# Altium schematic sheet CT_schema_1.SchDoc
size 522 x 479 mm
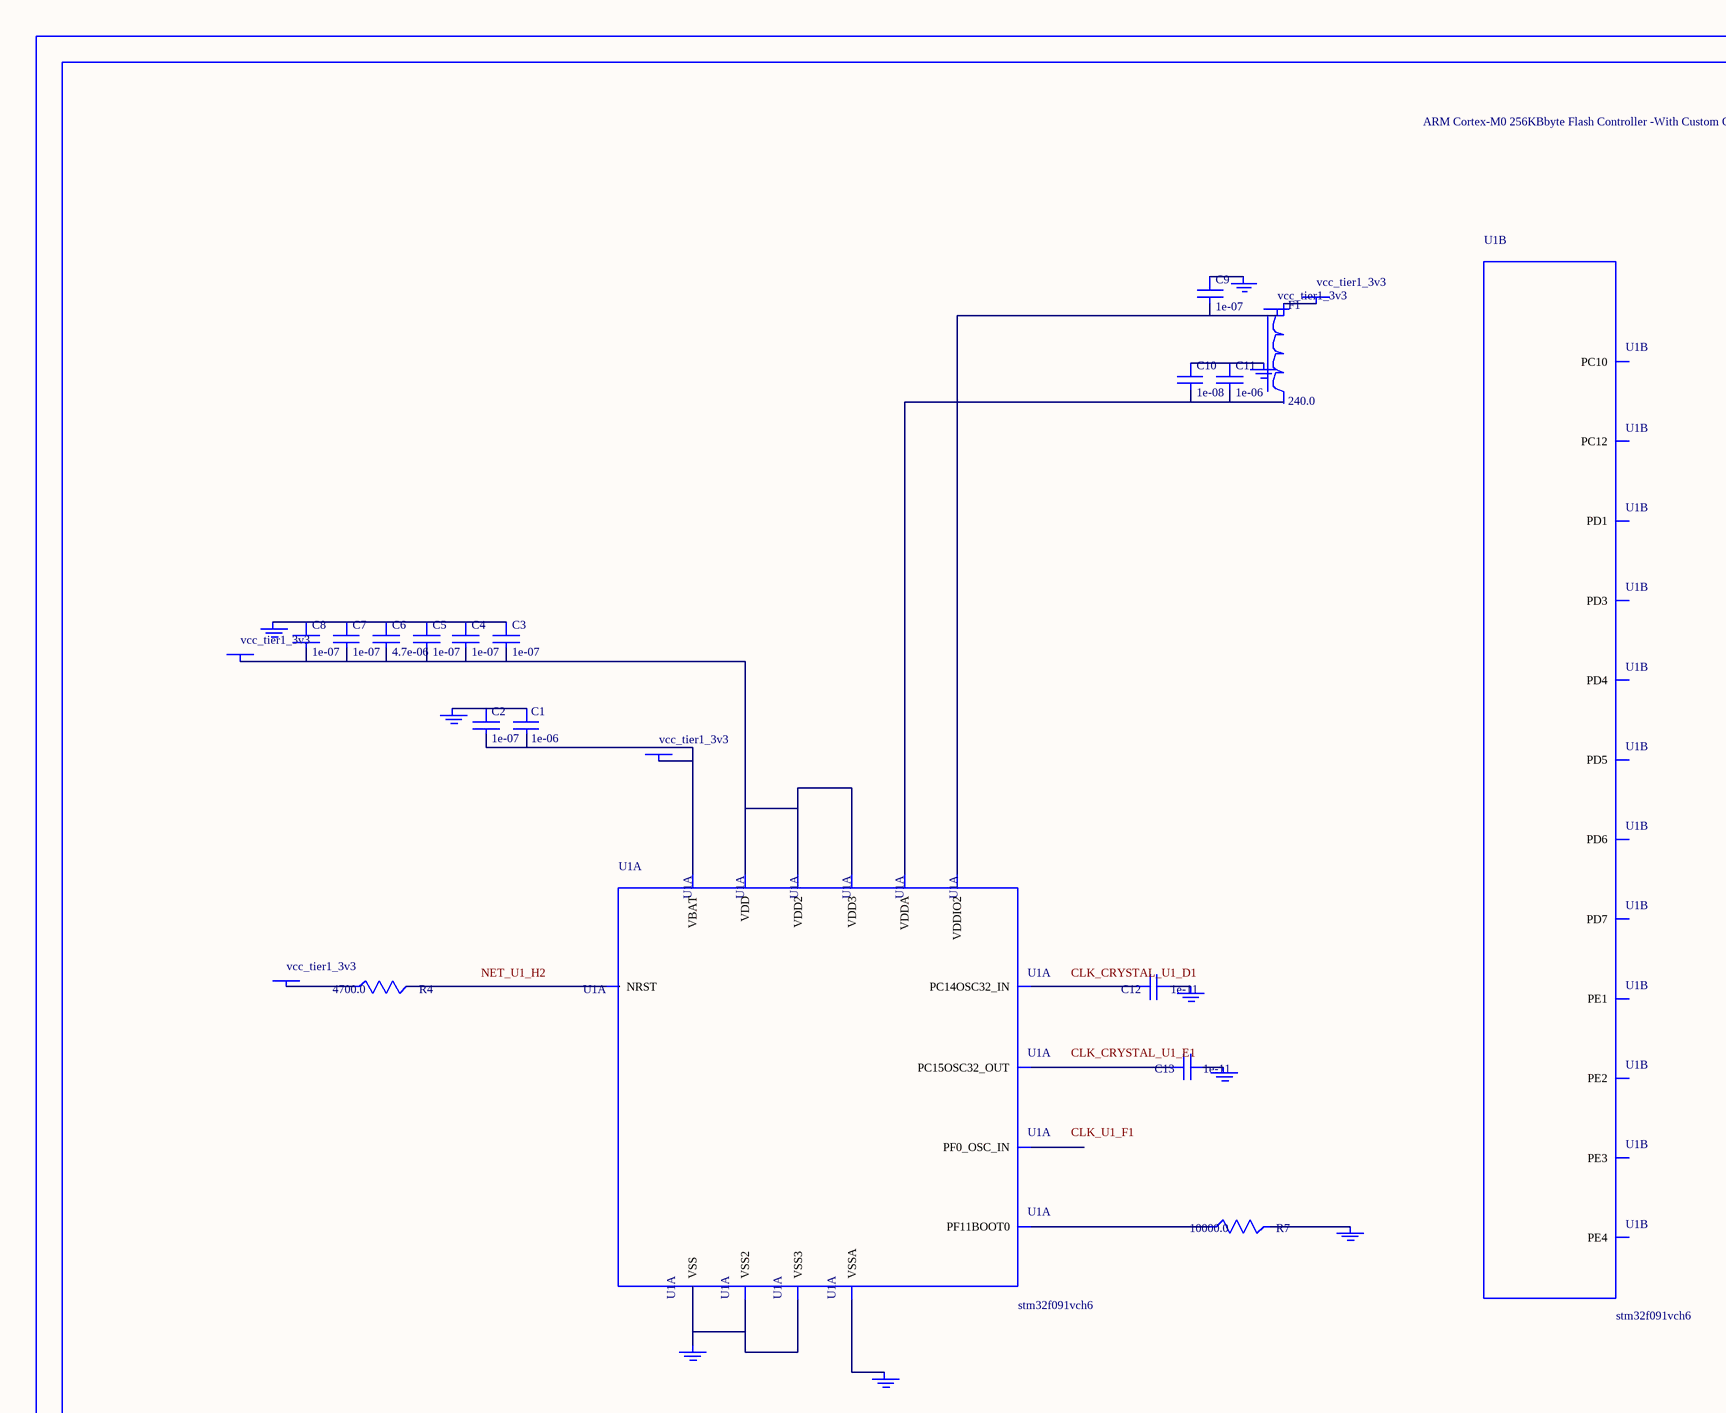
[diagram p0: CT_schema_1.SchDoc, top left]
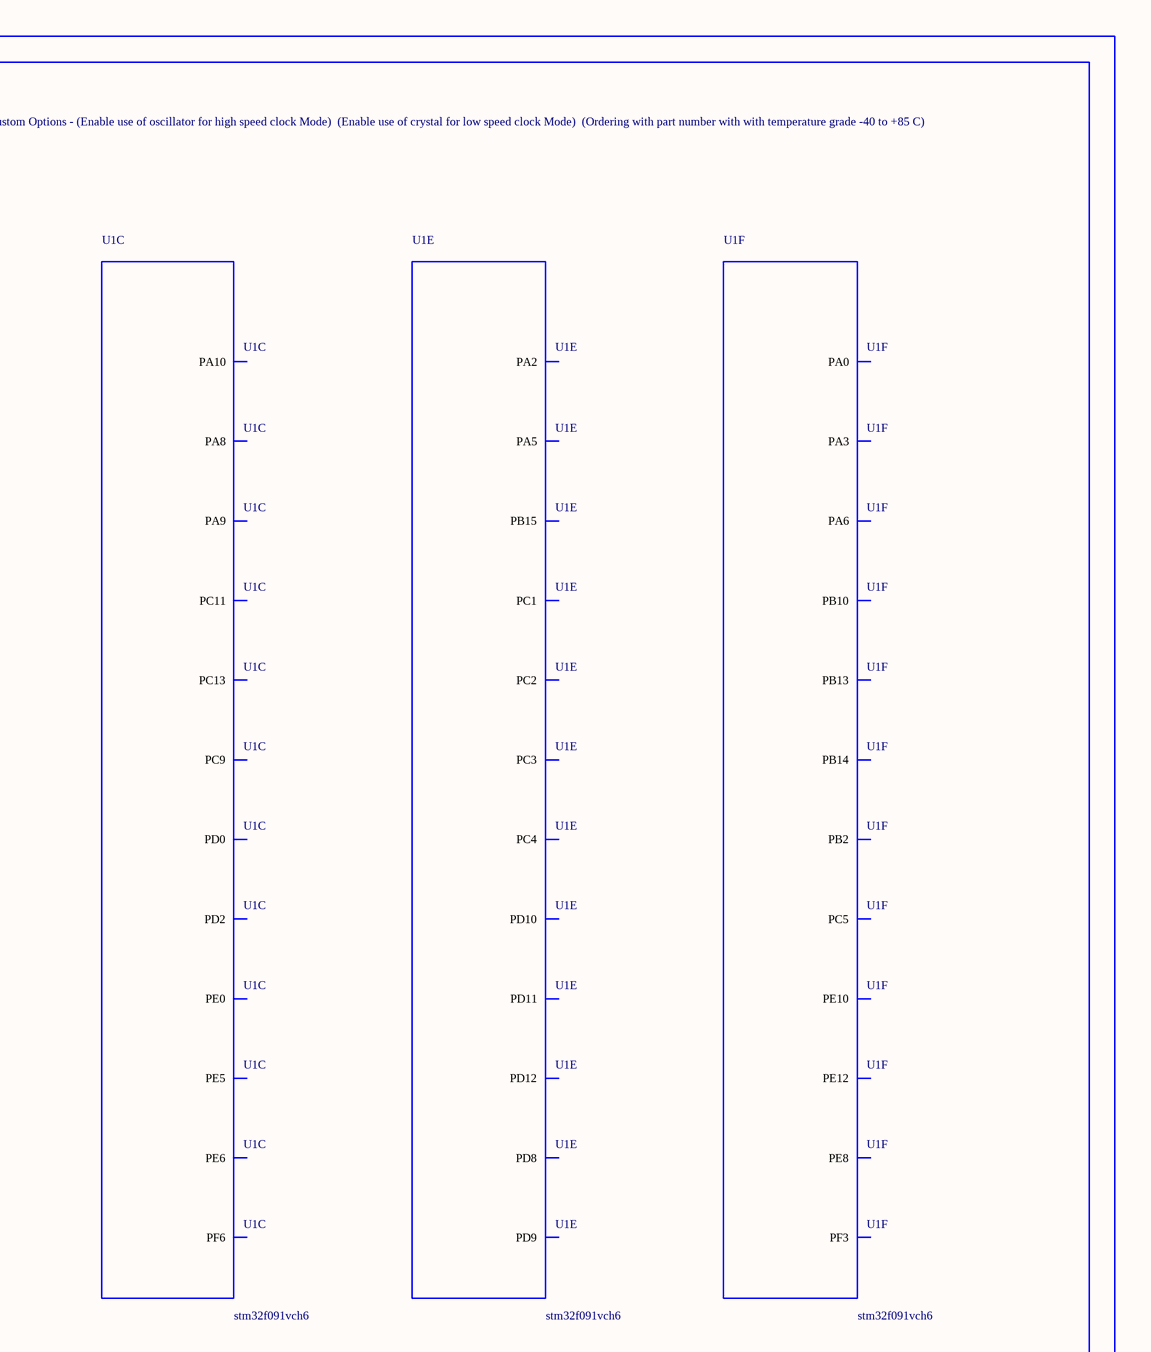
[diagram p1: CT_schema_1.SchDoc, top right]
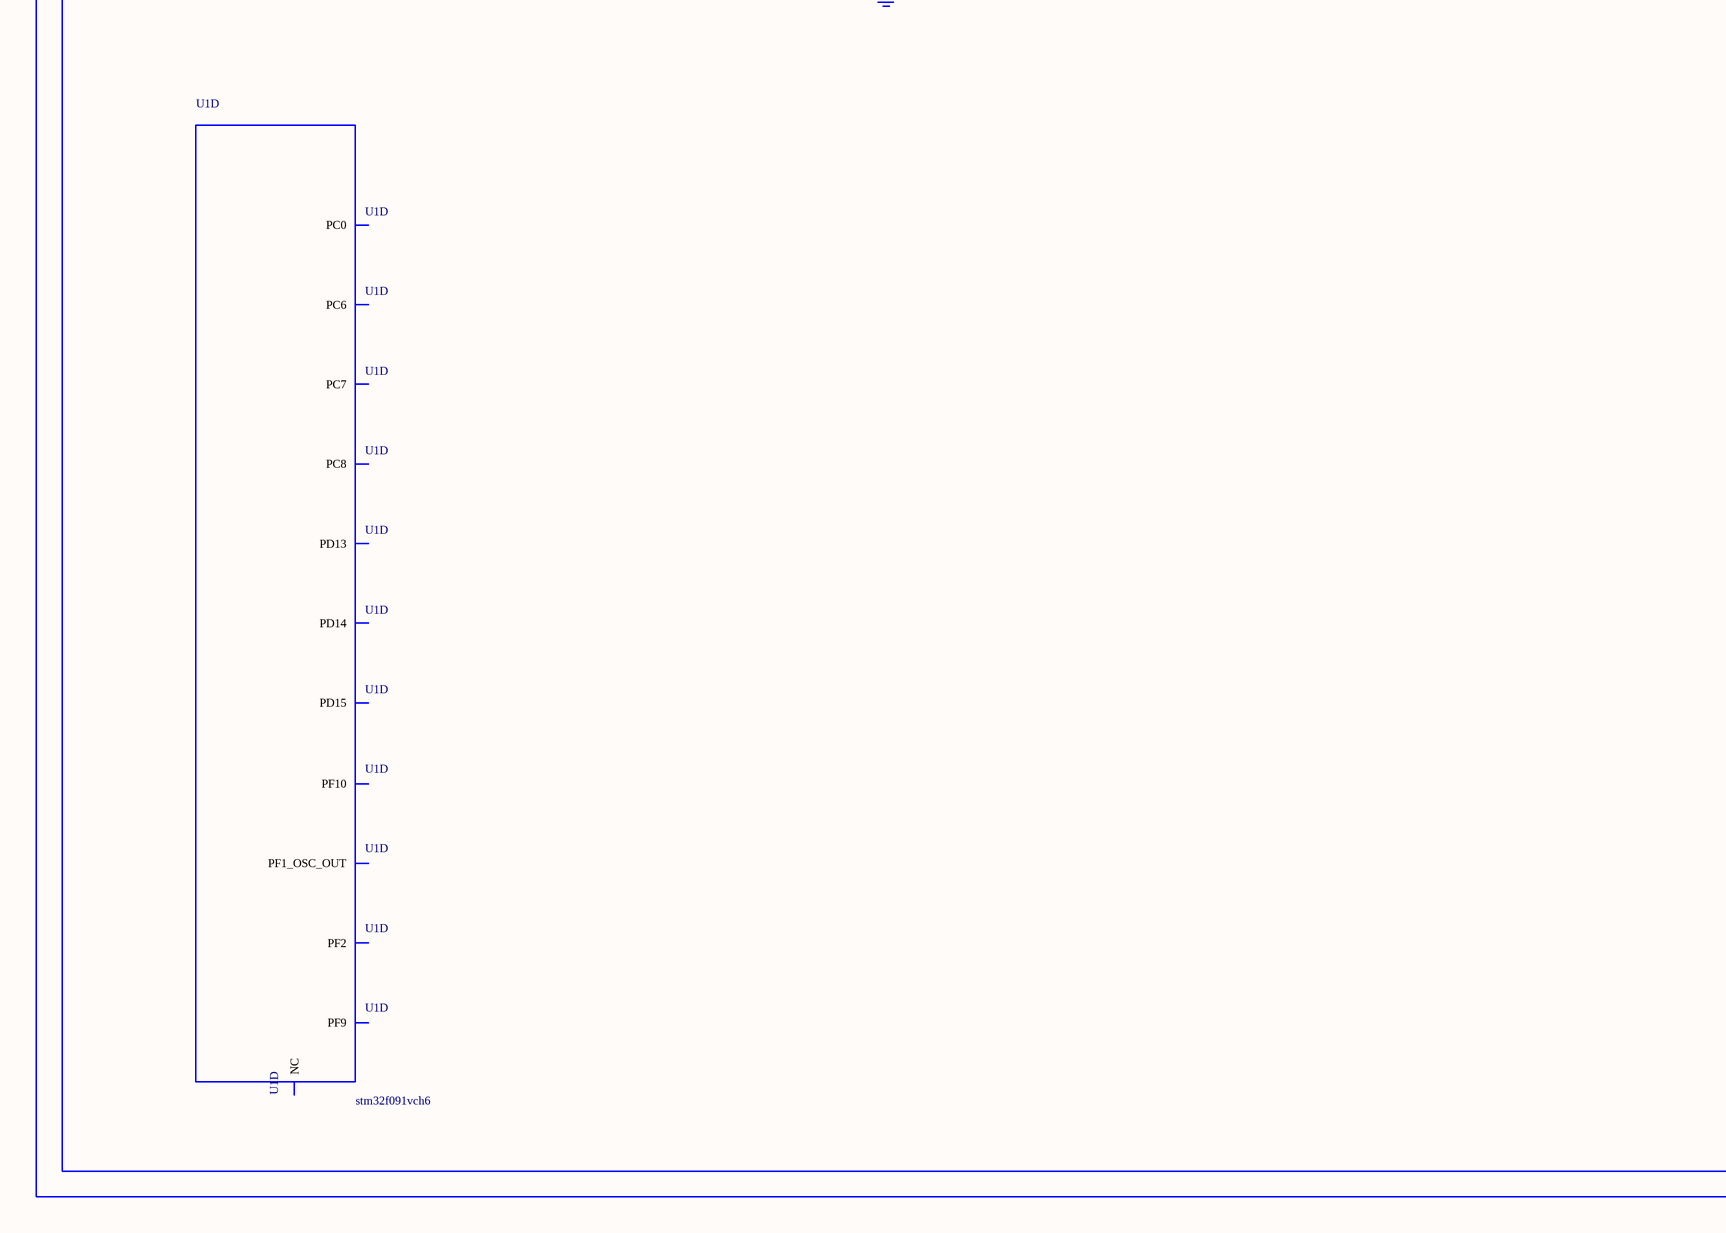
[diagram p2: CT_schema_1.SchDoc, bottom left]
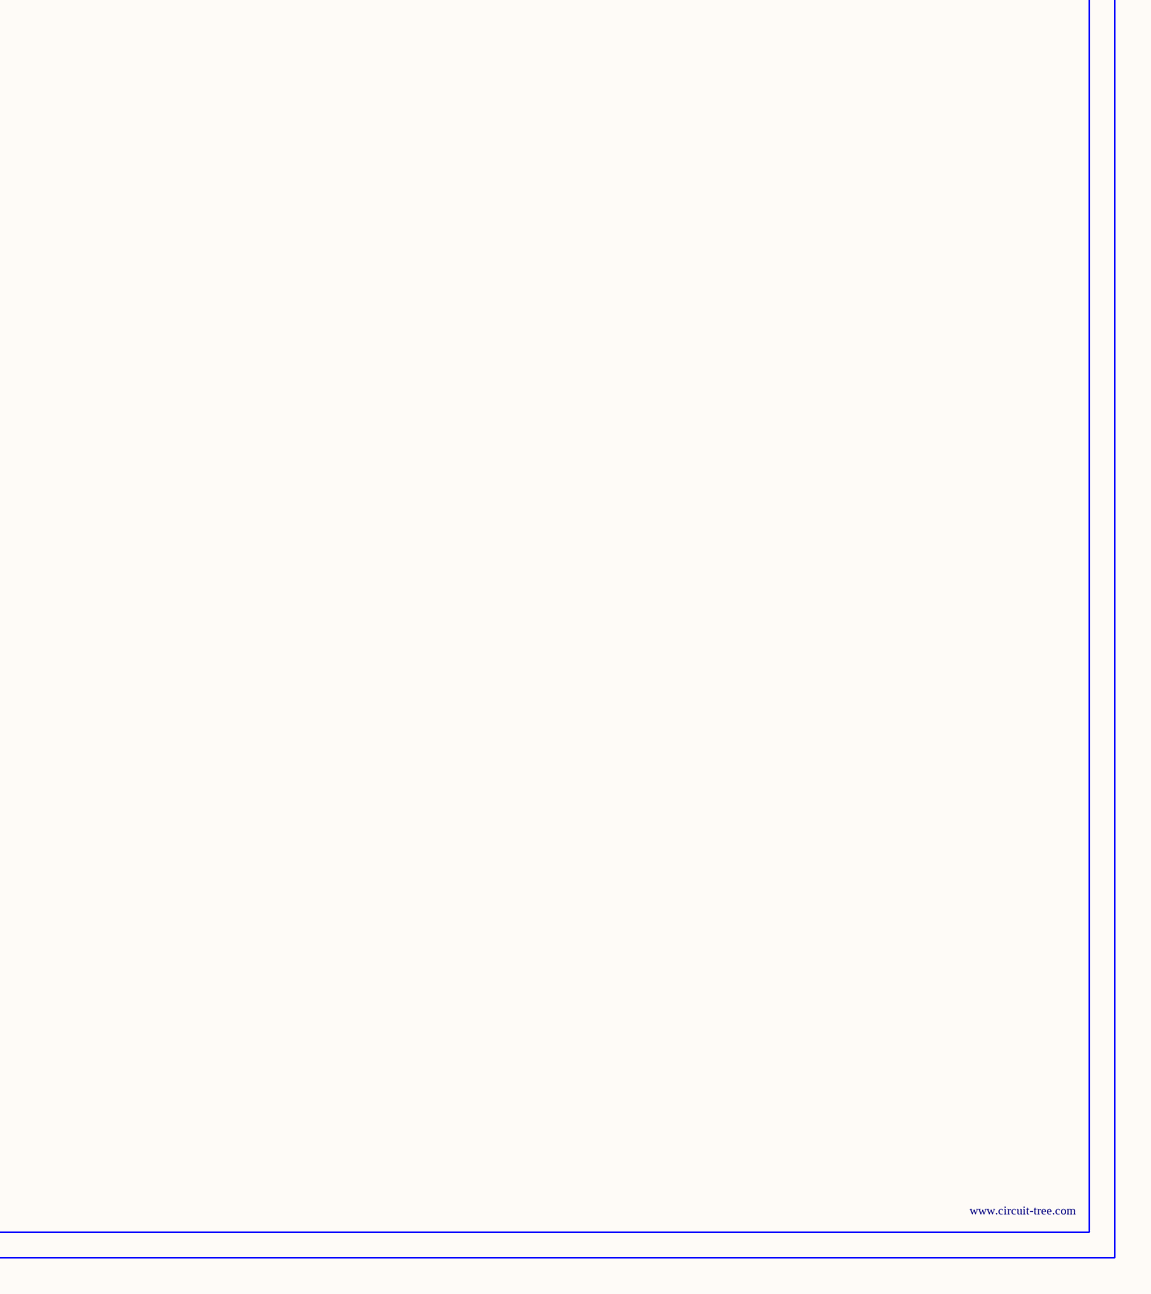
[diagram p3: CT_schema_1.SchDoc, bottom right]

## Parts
BORDER0  (no value)
C1  1e-06  [C0603]
C2  1e-07  [C0603]
C3  1e-07  [C0603]
C4  1e-07  [C0603]
C5  1e-07  [C0603]
C6  4.7e-06  [C0603]
C7  1e-07  [C0603]
C8  1e-07  [C0603]
C9  1e-07  [C0603]
C10  1e-08  [C0603]
C11  1e-06  [C0603]
C12  1e-11  [C0402]
C13  1e-11  [C0402]
F1  240.0  [L0603]
GND_INSTANCE_0_0  (no value)
GND_INSTANCE_0_1  (no value)
GND_INSTANCE_0_2  (no value)
GND_INSTANCE_0_3  (no value)
GND_INSTANCE_0_4  (no value)
GND_INSTANCE_0_5  (no value)
GND_INSTANCE_0_6  (no value)
GND_INSTANCE_0_7  (no value)
GND_INSTANCE_0_8  (no value)
POWER_INSTANCE_0_0  vcc_tier1_3v3
POWER_INSTANCE_0_1  vcc_tier1_3v3
POWER_INSTANCE_0_2  vcc_tier1_3v3
POWER_INSTANCE_0_3  vcc_tier1_3v3
POWER_INSTANCE_0_4  vcc_tier1_3v3
R4  4700.0  [R0603]
R7  10000.0  [R0603]
U1  stm32f091vch6  [UFBGA100]  (parts A,B,C,D,E,F of 9)

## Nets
NetC1_1: C1.1 C2.1 GND_INSTANCE_0_0.0(GND)
NetC1_2: C1.2 C2.2 POWER_INSTANCE_0_0.0(PWR) U1.E2(VBAT)
NetC3_1: C3.1 C4.1 C5.1 C6.1 C7.1 C8.1 GND_INSTANCE_0_2.0(GND)
NetC3_2: C3.2 C4.2 C5.2 C6.2 C7.2 C8.2 POWER_INSTANCE_0_2.0(PWR) U1.C4(VDD) U1.G12(VDD2) U1.H3(VDD3)
NetC9_1: C9.1 GND_INSTANCE_0_3.0(GND)
NetC9_2: C9.2 POWER_INSTANCE_0_3.0(PWR) U1.G11(VDDIO2)
NetC10_1: C10.1 C11.1 GND_INSTANCE_0_1.0(GND)
NetC10_2: C10.2 C11.2 U1.M1(VDDA)
NetC12_1: C12.1 GND_INSTANCE_0_5.0(GND)
NetC12_2: C12.2 U1.D1(PC14OSC32_IN)
NetC13_1: C13.1 GND_INSTANCE_0_6.0(GND)
NetC13_2: C13.2 U1.E1(PC15OSC32_OUT)
NetF1_1: F1.1 POWER_INSTANCE_0_1.0(PWR)
NetGND_INSTANCE_0_4_0: GND_INSTANCE_0_4.0(GND) R7.2
NetGND_INSTANCE_0_7_0: GND_INSTANCE_0_7.0(GND) U1.K1(VSSA)
NetGND_INSTANCE_0_8_0: GND_INSTANCE_0_8.0(GND) U1.D3(VSS) U1.F11(VSS2) U1.F12(VSS3)
NetPOWER_INSTANCE_0_4_0: POWER_INSTANCE_0_4.0(PWR) R4.1
NetR4_2: R4.2 U1.H2(NRST)
NetR7_1: R7.1 U1.A4(PF11BOOT0)

Not connected (* = marked no-connect by the designer): F1 2; U1 A1(PE3) A2(PE1) A5(PD7) A6(PD5) B1(PE4) B2(PE2) B6(PD6) B7(PD4) B8(PD3) B9(PD1) B10(PC12) B11(PC10) C1(PC13) C2(PE5) C3(PE0) C8(PD2) C9(PD0) C10(PC11) C11(PF6) C12(PA10) D2(PE6) D10(PA9) D11(PA8) D12(PC9) E3(NC) E10(PC8) E11(PC7) E12(PC6) F1(PF0_OSC_IN) F2(PF9) G1(PF1_OSC_OUT) G2(PF10) H1(PC0) H10(PD15) H11(PD14) H12(PD13) J1(PF2) J2(PC1) J3(PC2) J10(PD12) J11(PD11) J12(PD10) K2(PC3) K3(PA2) K4(PA5) K5(PC4) K8(PD9) K9(PD8) K10(PB15) K11(PB14) K12(PB13) L1(PF3) L2(PA0) L3(PA3) L4(PA6) L5(PC5) L6(PB2) L7(PE8) L8(PE10) L9(PE12) L10(PB10)

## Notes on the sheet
- Labels drawn without touching a wire or pin: CLK_CRYSTAL_U1_D1, CLK_CRYSTAL_U1_E1, CLK_U1_F1, NET_U1_H2

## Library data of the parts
BORDER0 = BORDER_PAGE0
C1 C11 = C0603C105K3RACTU
C2-C5 C7-C9 = 06035C104K4Z2A
C6 = GRM188R6YA475KE15D
C10 = 06035C103K4Z2A
C12 C13 = C0402C100K3GACTU
F1 = Z0603C241ASMST
GND_INSTANCE_0_0-GND_INSTANCE_0_8 = GND
POWER_INSTANCE_0_0-POWER_INSTANCE_0_4 = PWR
R4 = RC0603JR-074K7L
R7 = RC0603JR-0710KL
